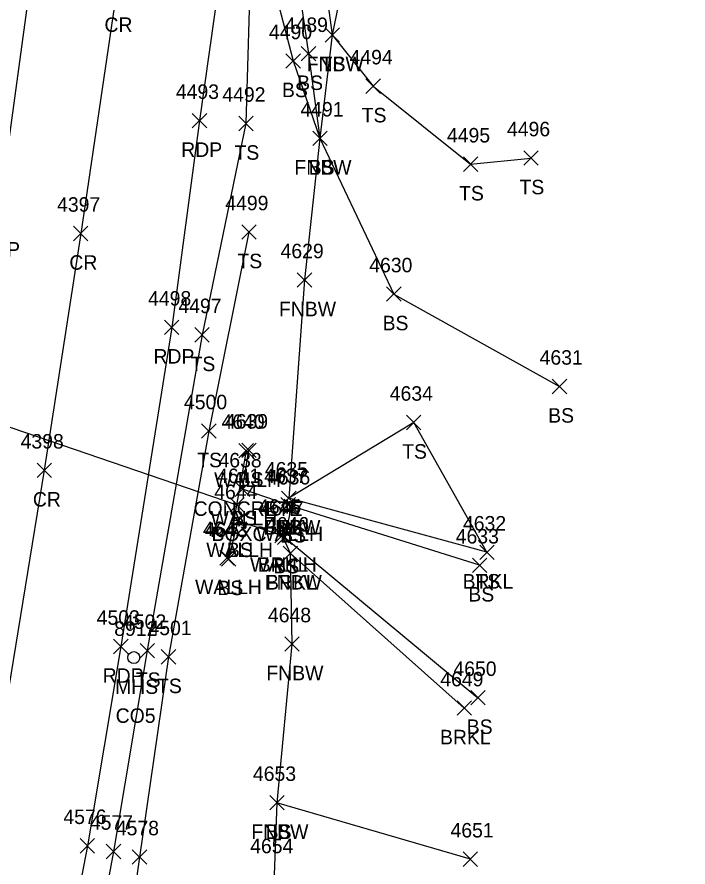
# Model space of a CAD drawing. Extents: x 1678863 to 1683592, y 407783 to 418211.
# Drawn here: x 1680267.7 to 1680360.3, y 412706.9 to 412824.2 of the extents above; entities that cross this region are included whole.
import ezdxf

# ---------------------------------------------------------------- set-up
doc = ezdxf.new("R2010")
doc.units = 0
for name, color, linetype in [('D_A', 7, 'Continuous'), ('D_C', 7, 'Continuous'), ('D_I', 7, 'Continuous'), ('D_TIC', 7, 'Continuous'), ('DDEFAULT', 7, 'Continuous'), ('DHW', 7, 'Continuous'), ('L_A', 7, 'Continuous'), ('L_I', 7, 'Continuous'), ('L_TIC', 7, 'Continuous'), ('LAWE', 7, 'Continuous'), ('LELB', 7, 'Continuous'), ('LFNC', 7, 'Continuous'), ('P_A', 7, 'Continuous'), ('P_I', 7, 'Continuous'), ('P_TIC', 7, 'Continuous'), ('PET', 7, 'Continuous'), ('PRC', 7, 'Continuous'), ('U_A', 7, 'Continuous'), ('U_C', 7, 'Continuous'), ('U_I', 7, 'Continuous'), ('USMH', 7, 'Continuous')]:
    doc.layers.add(name, color=color, linetype=linetype)

msp = doc.modelspace()

# ---------------------------------------------------------------- linework, layer by layer
at = {"layer": 'D_TIC'}
for points in [[(1680298.35, 412763.36), (1680300.35, 412765.36)], [(1680300.35, 412763.36), (1680298.35, 412765.36)], [(1680297.85, 412758.05), (1680299.85, 412760.05)], [(1680299.85, 412758.05), (1680297.85, 412760.05)], [(1680297.09, 412755.89), (1680299.09, 412757.89)], [(1680299.09, 412755.89), (1680297.09, 412757.89)], [(1680304.16, 412755.89), (1680306.16, 412757.89)], [(1680306.16, 412755.89), (1680304.16, 412757.89)], [(1680297.26, 412753.68), (1680299.26, 412755.68)], [(1680299.26, 412753.68), (1680297.26, 412755.68)], [(1680303.3, 412751.65), (1680305.3, 412753.65)], [(1680305.3, 412751.65), (1680303.3, 412753.65)], [(1680295.72, 412748.57), (1680297.72, 412750.57)], [(1680297.72, 412748.57), (1680295.72, 412750.57)]]:
    msp.add_lwpolyline(points, dxfattribs=at)
at = {"layer": 'DDEFAULT'}
msp.add_lwpolyline([(1680254.88, 412771.66), (1680298.09, 412756.89)], dxfattribs=at)
at = {"layer": 'DHW'}
for points in [[(1680299.35, 412764.36), (1680296.72, 412749.57)], [(1680305.16, 412756.89), (1680298.85, 412759.05)], [(1680298.26, 412754.68), (1680304.3, 412752.65)]]:
    msp.add_lwpolyline(points, dxfattribs=at)
at = {"layer": 'L_TIC'}
for points in [[(1680310.23, 412820.7), (1680312.23, 412822.7)], [(1680312.23, 412820.7), (1680310.23, 412822.7)], [(1680310.23, 412820.7), (1680312.23, 412822.7)], [(1680312.23, 412820.7), (1680310.23, 412822.7)], [(1680306.95, 412818.11), (1680308.95, 412820.11)], [(1680308.95, 412818.11), (1680306.95, 412820.11)], [(1680304.84, 412817.12), (1680306.84, 412819.12)], [(1680306.84, 412817.12), (1680304.84, 412819.12)], [(1680315.88, 412813.64), (1680317.88, 412815.64)], [(1680317.88, 412813.64), (1680315.88, 412815.64)], [(1680298.33, 412808.49), (1680300.33, 412810.49)], [(1680300.33, 412808.49), (1680298.33, 412810.49)], [(1680308.53, 412806.45), (1680310.53, 412808.45)], [(1680310.53, 412806.45), (1680308.53, 412808.45)], [(1680308.53, 412806.45), (1680310.53, 412808.45)], [(1680310.53, 412806.45), (1680308.53, 412808.45)], [(1680308.53, 412806.45), (1680310.53, 412808.45)], [(1680310.53, 412806.45), (1680308.53, 412808.45)], [(1680337.64, 412803.72), (1680339.64, 412805.72)], [(1680339.64, 412803.72), (1680337.64, 412805.72)], [(1680329.31, 412802.87), (1680331.31, 412804.87)], [(1680331.31, 412802.87), (1680329.31, 412804.87)], [(1680298.74, 412793.52), (1680300.74, 412795.52)], [(1680300.74, 412793.52), (1680298.74, 412795.52)], [(1680306.41, 412786.9), (1680308.41, 412788.9)], [(1680308.41, 412786.9), (1680306.41, 412788.9)], [(1680318.72, 412784.96), (1680320.72, 412786.96)], [(1680320.72, 412784.96), (1680318.72, 412786.96)], [(1680292.27, 412779.33), (1680294.27, 412781.33)], [(1680294.27, 412779.33), (1680292.27, 412781.33)], [(1680341.57, 412772.22), (1680343.57, 412774.22)], [(1680343.57, 412772.22), (1680341.57, 412774.22)], [(1680321.46, 412767.25), (1680323.46, 412769.25)], [(1680323.46, 412767.25), (1680321.46, 412769.25)], [(1680293.2, 412766.07), (1680295.2, 412768.07)], [(1680295.2, 412766.07), (1680293.2, 412768.07)], [(1680298.74, 412763.41), (1680300.74, 412765.41)], [(1680300.74, 412763.41), (1680298.74, 412765.41)], [(1680297.85, 412758.05), (1680299.85, 412760.05)], [(1680299.85, 412758.05), (1680297.85, 412760.05)], [(1680304.25, 412756.79), (1680306.25, 412758.79)], [(1680306.25, 412756.79), (1680304.25, 412758.79)], [(1680304.25, 412756.79), (1680306.25, 412758.79)], [(1680306.25, 412756.79), (1680304.25, 412758.79)], [(1680304.25, 412756.79), (1680306.25, 412758.79)], [(1680306.25, 412756.79), (1680304.25, 412758.79)], [(1680304.61, 412755.69), (1680306.61, 412757.69)], [(1680306.61, 412755.69), (1680304.61, 412757.69)], [(1680297.26, 412753.68), (1680299.26, 412755.68)], [(1680299.26, 412753.68), (1680297.26, 412755.68)], [(1680303.3, 412751.65), (1680305.3, 412753.65)], [(1680305.3, 412751.65), (1680303.3, 412753.65)], [(1680303.66, 412751.43), (1680305.66, 412753.43)], [(1680305.66, 412751.43), (1680303.66, 412753.43)], [(1680331.57, 412749.34), (1680333.57, 412751.34)], [(1680333.57, 412749.34), (1680331.57, 412751.34)], [(1680331.57, 412749.34), (1680333.57, 412751.34)], [(1680333.57, 412749.34), (1680331.57, 412751.34)], [(1680295.95, 412748.43), (1680297.95, 412750.43)], [(1680297.95, 412748.43), (1680295.95, 412750.43)], [(1680304.44, 412749.2), (1680306.44, 412751.2)], [(1680306.44, 412749.2), (1680304.44, 412751.2)], [(1680304.44, 412749.2), (1680306.44, 412751.2)], [(1680306.44, 412749.2), (1680304.44, 412751.2)], [(1680330.56, 412747.55), (1680332.56, 412749.55)], [(1680332.56, 412747.55), (1680330.56, 412749.55)], [(1680304.67, 412736.68), (1680306.67, 412738.68)], [(1680306.67, 412736.68), (1680304.67, 412738.68)], [(1680284.72, 412735.77), (1680286.72, 412737.77)], [(1680286.72, 412735.77), (1680284.72, 412737.77)], [(1680287.65, 412734.91), (1680289.65, 412736.91)], [(1680289.65, 412734.91), (1680287.65, 412736.91)], [(1680330.33, 412729.28), (1680332.33, 412731.28)], [(1680332.33, 412729.28), (1680330.33, 412731.28)], [(1680328.44, 412727.85), (1680330.44, 412729.85)], [(1680330.44, 412727.85), (1680328.44, 412729.85)], [(1680302.6, 412714.8), (1680304.6, 412716.8)], [(1680304.6, 412714.8), (1680302.6, 412716.8)], [(1680302.6, 412714.8), (1680304.6, 412716.8)], [(1680304.6, 412714.8), (1680302.6, 412716.8)], [(1680280.06, 412708.07), (1680282.06, 412710.07)], [(1680282.06, 412708.07), (1680280.06, 412710.07)], [(1680283.64, 412707.3), (1680285.64, 412709.3)], [(1680285.64, 412707.3), (1680283.64, 412709.3)], [(1680329.28, 412707), (1680331.28, 412709)], [(1680331.28, 412707), (1680329.28, 412709)]]:
    msp.add_lwpolyline(points, dxfattribs=at)
at = {"layer": 'LAWE'}
for points in [[(1680332.57, 412750.34), (1680305.25, 412757.79)], [(1680304.3, 412752.65), (1680305.44, 412750.2), (1680329.44, 412728.85)]]:
    msp.add_lwpolyline(points, dxfattribs=at)
at = {"layer": 'LELB'}
for points in [[(1680360.29, 413161.28), (1680345.78, 413139.8), (1680335.33, 413115.86), (1680325.49, 413080.45), (1680319.55, 413036.54), (1680322.7, 413006.17), (1680318.49, 412958.65), (1680310.76, 412916.79), (1680306.66, 412870.7), (1680302.03, 412832.78), (1680305.84, 412818.12), (1680309.53, 412807.45), (1680319.72, 412785.96), (1680342.57, 412773.22)], [(1680334.53, 413145.5), (1680320.16, 413118.16), (1680317.14, 413080.04), (1680314.23, 413037.22), (1680312.09, 413006.9), (1680310.05, 412958.33), (1680307.29, 412917.85), (1680302.46, 412870.5), (1680300, 412833.06), (1680299.33, 412809.49), (1680293.27, 412780.33), (1680285.72, 412736.77), (1680281.06, 412709.07), (1680273.24, 412667.09), (1680267.95, 412624.5), (1680272.36, 412614.56), (1680289.47, 412595.96), (1680300.87, 412585.11)], [(1680306.66, 412870.7), (1680306.08, 412832), (1680307.95, 412819.11), (1680309.53, 412807.45)], [(1680317.63, 412849.02), (1680311.25, 412859.59), (1680307.9, 412845.95), (1680311.23, 412821.7), (1680316.88, 412814.64), (1680330.31, 412803.87), (1680338.64, 412804.72)], [(1680299.74, 412794.52), (1680294.2, 412767.07), (1680288.65, 412735.91), (1680284.64, 412708.3), (1680278.57, 412665.38), (1680272.21, 412623.34), (1680274.75, 412616.44), (1680289.5, 412607.06)], [(1680332.57, 412750.34), (1680322.46, 412768.25), (1680305.25, 412757.79)], [(1680298.85, 412759.05), (1680299.74, 412764.41)], [(1680331.56, 412748.55), (1680305.61, 412756.69), (1680304.66, 412752.43), (1680331.33, 412730.28)], [(1680296.95, 412749.43), (1680298.26, 412754.68)], [(1680330.28, 412708), (1680303.6, 412715.8)]]:
    msp.add_lwpolyline(points, dxfattribs=at)
at = {"layer": 'LFNC'}
for points in [[(1680313.98, 412835.09), (1680311.23, 412821.7), (1680309.53, 412807.45), (1680307.41, 412787.9), (1680305.25, 412757.79)], [(1680305.44, 412750.2), (1680305.67, 412737.68), (1680303.6, 412715.8), (1680303.22, 412705.83), (1680299.4, 412669.77), (1680296.09, 412637.68), (1680294.05, 412608.2), (1680295.71, 412595.23)]]:
    msp.add_lwpolyline(points, dxfattribs=at)
at = {"layer": 'P_TIC'}
for points in [[(1680291.92, 412808.88), (1680293.92, 412810.88)], [(1680293.92, 412808.88), (1680291.92, 412810.88)], [(1680275.54, 412793.32), (1680277.54, 412795.32)], [(1680277.54, 412793.32), (1680275.54, 412795.32)], [(1680288.09, 412780.37), (1680290.09, 412782.37)], [(1680290.09, 412780.37), (1680288.09, 412782.37)], [(1680270.51, 412760.65), (1680272.51, 412762.65)], [(1680272.51, 412760.65), (1680270.51, 412762.65)], [(1680281.07, 412736.34), (1680283.07, 412738.34)], [(1680283.07, 412736.34), (1680281.07, 412738.34)], [(1680276.46, 412708.86), (1680278.46, 412710.86)], [(1680278.46, 412708.86), (1680276.46, 412710.86)]]:
    msp.add_lwpolyline(points, dxfattribs=at)
at = {"layer": 'PET'}
for points in [[(1680296.3, 412834.01), (1680292.92, 412809.88), (1680289.09, 412781.37), (1680282.07, 412737.34), (1680277.46, 412709.86), (1680269.38, 412667.98), (1680262.24, 412629.4), (1680258.01, 412607.41), (1680253.6, 412586.01), (1680248.62, 412559.86), (1680242.91, 412531.6), (1680235.26, 412492.91), (1680227.56, 412454.34), (1680216.99, 412407.09), (1680207.45, 412367.83), (1680196.86, 412331.66), (1680189.42, 412308.79), (1680178.4, 412278.7), (1680165.09, 412243.62)], [(1680269.63, 412829.2), (1680265.04, 412796.13), (1680259.96, 412765.02), (1680256.28, 412741.52), (1680251.79, 412716.36), (1680243.91, 412672.27), (1680235.73, 412631.6), (1680228.05, 412591.55), (1680223.07, 412565.97), (1680218.11, 412539.91), (1680211.61, 412508.58), (1680205.85, 412480.93), (1680199.66, 412448.83), (1680195.01, 412427.07), (1680186.54, 412390.39), (1680175.26, 412348.31), (1680163.41, 412311.1), (1680153.81, 412285.2), (1680145.32, 412262.57), (1680136.24, 412241.39)]]:
    msp.add_lwpolyline(points, dxfattribs=at)
at = {"layer": 'PRC'}
msp.add_lwpolyline([(1680281.38, 412827.12), (1680276.54, 412794.32), (1680271.51, 412761.65), (1680263.6, 412713.37), (1680255.9, 412669.93), (1680248.46, 412629.97), (1680240.84, 412588.83), (1680235.69, 412562.84), (1680230.13, 412534.53), (1680222.13, 412495.39), (1680214.42, 412458.66), (1680203.73, 412409.82), (1680194.11, 412372.14), (1680183.59, 412335.84), (1680176.01, 412313.28), (1680165.53, 412283.79), (1680155.94, 412258.65)], dxfattribs=at)
at = {"layer": 'USMH'}
for p, q in [((1680283.85, 412735.81), (1680283.85, 412735.81)), ((1680284.68, 412735.81), (1680284.68, 412735.81))]:
    msp.add_line(p, q, dxfattribs=at)
msp.add_circle((1680283.85, 412735.81), 0.833, dxfattribs=at)

# ---------------------------------------------------------------- texts
at = {"layer": 'D_A'}
for s, p in [('WALLH', (1680294.94, 412759.36)), ('WALLH', (1680294.44, 412754.05)), ('BOXC', (1680294.58, 412751.89)), ('WALLH', (1680300.75, 412751.89)), ('WALLH', (1680293.85, 412749.68)), ('WALLH', (1680299.89, 412747.65)), ('WALLH', (1680292.31, 412744.57))]:
    msp.add_text(s, height=2, dxfattribs=at).set_placement(p)
at = {"layer": 'D_C'}
msp.add_text('CONCRETE', height=2, dxfattribs=at).set_placement((1680292.1, 412755.36))
at = {"layer": 'D_I'}
for s, p in [('4640', (1680295.95, 412767.36)), ('4638', (1680295.54, 412762.05)), ('4641', (1680295.35, 412759.89)), ('4637', (1680301.85, 412759.89)), ('4644', (1680294.95, 412757.68)), ('4645', (1680301, 412755.65)), ('4642', (1680293.41, 412752.57))]:
    msp.add_text(s, height=2, dxfattribs=at).set_placement(p)
at = {"layer": 'L_A'}
for s, p in [('FNBW', (1680307.7, 412816.7)), ('TS', (1680309.64, 412816.7)), ('BS', (1680306.39, 412814.11)), ('BS', (1680304.29, 412813.12)), ('TS', (1680315.29, 412809.64)), ('TS', (1680297.74, 412804.49)), ('FNBW', (1680306.01, 412802.45)), ('BS', (1680307.98, 412802.45)), ('BS', (1680307.98, 412802.45)), ('TS', (1680337.05, 412799.72)), ('TS', (1680328.72, 412798.87)), ('TS', (1680298.15, 412789.52)), ('FNBW', (1680303.88, 412782.9)), ('BS', (1680318.17, 412780.96)), ('TS', (1680291.68, 412775.33)), ('BS', (1680341.01, 412768.22)), ('TS', (1680320.87, 412763.25)), ('TS', (1680292.61, 412762.07)), ('BS', (1680298.18, 412759.41)), ('BS', (1680297.29, 412754.05)), ('FNBW', (1680301.72, 412752.79)), ('BRKL', (1680301.89, 412752.79)), ('TS', (1680303.66, 412752.79)), ('BS', (1680304.05, 412751.69)), ('BS', (1680296.7, 412749.68)), ('BRKL', (1680300.95, 412747.65)), ('BS', (1680303.1, 412747.43)), ('FNBW', (1680301.92, 412745.2)), ('BRKL', (1680302.09, 412745.2)), ('BRKL', (1680329.21, 412745.34)), ('TS', (1680330.98, 412745.34)), ('BS', (1680295.39, 412744.43)), ('BS', (1680330, 412743.55)), ('TS', (1680284.13, 412731.77)), ('FNBW', (1680302.14, 412732.68)), ('TS', (1680287.06, 412730.91)), ('BS', (1680329.78, 412725.28)), ('BRKL', (1680326.09, 412723.85)), ('FNBW', (1680300.07, 412710.8)), ('BS', (1680302.04, 412710.8))]:
    msp.add_text(s, height=2, dxfattribs=at).set_placement(p)
at = {"layer": 'L_I'}
for s, p in [('4489', (1680304.68, 412822.11)), ('4490', (1680302.5, 412821.12)), ('4494', (1680313.62, 412817.64)), ('4492', (1680296.07, 412812.49)), ('4491', (1680306.84, 412810.45)), ('4491', (1680306.84, 412810.45)), ('4491', (1680306.84, 412810.45)), ('4495', (1680327.05, 412806.87)), ('4496', (1680335.33, 412807.72)), ('4499', (1680296.48, 412797.52)), ('4629', (1680304.1, 412790.9)), ('4630', (1680316.33, 412788.96)), ('4497', (1680290.01, 412783.33)), ('4631', (1680339.83, 412776.22)), ('4634', (1680319.16, 412771.25)), ('4500', (1680290.78, 412770.07)), ('4639', (1680296.43, 412767.41)), ('4638', (1680295.54, 412762.05)), ('4635', (1680301.94, 412760.79)), ('4635', (1680301.94, 412760.79)), ('4635', (1680301.94, 412760.79)), ('4636', (1680302.24, 412759.69)), ('4644', (1680294.95, 412757.68)), ('4645', (1680301, 412755.65)), ('4647', (1680301.35, 412755.43)), ('4646', (1680302.08, 412753.2)), ('4646', (1680302.08, 412753.2)), ('4632', (1680329.26, 412753.34)), ('4632', (1680329.26, 412753.34)), ('4643', (1680293.65, 412752.43)), ('4633', (1680328.26, 412751.55)), ('4648', (1680302.36, 412740.68)), ('4502', (1680282.38, 412739.77)), ('4501', (1680285.88, 412738.91)), ('4650', (1680327.94, 412733.28)), ('4649', (1680326.13, 412731.85)), ('4653', (1680300.29, 412718.8)), ('4653', (1680300.29, 412718.8)), ('4577', (1680277.8, 412712.07)), ('4578', (1680281.38, 412711.3)), ('4651', (1680327.54, 412711)), ('4654', (1680299.91, 412708.83)), ('4654', (1680299.91, 412708.83)), ('4654', (1680299.91, 412708.83))]:
    msp.add_text(s, height=2, dxfattribs=at).set_placement(p)
at = {"layer": 'P_A'}
for s, p in [('CR', (1680279.81, 412822.12)), ('RDP', (1680290.4, 412804.88)), ('RDP', (1680262.52, 412791.13)), ('CR', (1680274.97, 412789.32)), ('RDP', (1680286.57, 412776.37)), ('CR', (1680269.94, 412756.65)), ('RDP', (1680279.56, 412732.34))]:
    msp.add_text(s, height=2, dxfattribs=at).set_placement(p)
at = {"layer": 'P_I'}
for s, p in [('4493', (1680289.66, 412812.88)), ('4397', (1680273.28, 412797.32)), ('4498', (1680285.83, 412784.37)), ('4398', (1680268.25, 412764.65)), ('4503', (1680278.74, 412740.34)), ('4576', (1680274.15, 412712.86))]:
    msp.add_text(s, height=2, dxfattribs=at).set_placement(p)
at = {"layer": 'U_A'}
msp.add_text('MHS', height=2, dxfattribs=at).set_placement((1680281.27, 412730.81))
at = {"layer": 'U_C'}
msp.add_text('CO5', height=2, dxfattribs=at).set_placement((1680281.36, 412726.81))
at = {"layer": 'U_I'}
msp.add_text('8912', height=2, dxfattribs=at).set_placement((1680281.16, 412738.81))

doc.saveas('drawing.dxf')
